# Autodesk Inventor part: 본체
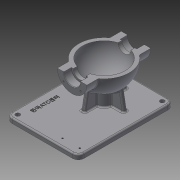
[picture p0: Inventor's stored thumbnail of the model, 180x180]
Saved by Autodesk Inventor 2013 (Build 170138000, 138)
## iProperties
Created: 2015-12
Part Number: 본체
Material: 일반
Document SubType Name: Modeling
Designer: mduedu
Density: 2.71 g/cm^3
Mass: 1330.63 g
Surface Area: 1128.56 cm^2
Volume: 491.008 cm^3
Author: mduedu
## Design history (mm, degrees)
sketch "스케치1"
  geometry: L1 (-53, 0)-(53, 0); A1 r 53 centre (0, 0) between (53, 0) and (-53, 0); 2 further points
  constraints: 2 coincident, 2 end point, 2 point on circle, 1 centre point, 1 horizontal, 1 midpoint
  dimensions: "d0" = 53 radius of A1
revolve "회전1" sketch "스케치1" stored, may be unused: angle "d2" = 90 deg
feature "쉘1" dims "d11" = 8
node "작업 평면1"
sketch "스케치2"
  geometry: C1 r 31 at (0, 0); 1 further point
  constraints: 1 centre point, 1 coincident
  dimensions: "d4" = 62 diameter of C1
extrude "돌출1" join sketch "스케치2" stored distance "d5" = 10; taper "d6" = 0 deg
hole "구멍1" diameter "d14" = 35; stored, may be unused: countersink angle "d18" = 90 deg, drill point angle "d20" = 0 deg; dims "d12" = 10, "d13" = 10, "d15" = 6, "d16" = 4, "d17" = 2, "d19" = 16
hole "구멍2" diameter "d23" = 27; stored, may be unused: countersink angle "d27" = 90 deg, drill point angle "d29" = 0 deg; dims "d21" = 10, "d22" = 10, "d24" = 6, "d25" = 4, "d26" = 2, "d28" = 16
fillet "모깎기1" dims "d30" = 0.3
chamfer "모따기1" distance "d40" = 1; stored, may be unused: second distance "d41" = 2, angle "d42" = 45 deg
sketch "스케치4"
  geometry: L1 (0, 0)-(0, -25); L2 (0, 0)-(-17.678, -17.678); A1 r 25 centre (0, 0) between (-17.678, -17.678) and (0, -25); 1 further point
  constraints: 4 end point, 2 point on circle, 1 centre point, 1 coincident, 1 vertical
  dimensions: "d43" = 50 diameter of A1; "d47" = 45 deg angle of L1 L2
hole "구멍4" sketch "스케치4" at (-17.678, -17.678) diameter "d49" = 3.242; stored, may be unused: countersink angle "d53" = 90 deg, drill point angle "d55" = 118 deg; dims "d50" = 11, "d51" = 4, "d52" = 2, "d54" = 13
node "작업 평면3"
sketch "스케치6" dims "d21" = 10, "d22" = 10
  geometry: L1 (-70, -75)-(130, -75); L2 (130, -75)-(130, 76); L3 (130, 76)-(-70, 76); L4 (-70, 76)-(-70, -75); 2 further points
  constraints: 8 end point, 2 parallel, 1 coincident, 1 horizontal, 1 perpendicular
  dimensions: "d158" = 200 distance of L3.end L2.end; "d159" = 151 distance of L2.end L1.end; "d162" = 75 distance from line of L1 point (0, 0); "d163" = 70 distance from line of L4 point (0, 0)
extrude "돌출3" join sketch "스케치6" distance "d80" = 10; taper "d81" = 0 deg
sketch "스케치7"
  geometry: C1 r 20 at (0, 0); 2 further points
  constraints: 2 coincident, 1 centre point
  dimensions: "d82" = 40 diameter of C1
extrude "돌출4" join sketch "스케치7" stored distance "d84" = 10; taper "d85" = 0 deg
sketch "스케치8"
  geometry: 3 further points
  constraints: 2 coincident
hole "구멍6" sketch "스케치8" at (0, 0) diameter "d86" = 20; stored, may be unused: countersink angle "d90" = 90 deg, drill point angle "d92" = 118 deg; dims "d87" = 7, "d88" = 40, "d89" = 5, "d91" = 10
fillet "모깎기2" dims "d93" = 0.3
sketch "스케치9"
  geometry: L1 (-45, -75)-(-38.245, -36.692); L2 (70, -75)-(-130, -75) reference; A1 r 53 centre (0, 0) between (42.988, 31) and (42.988, -31) reference; 1 further point
  constraints: 2 end point, 1 coincident, 1 point on circle, 1 point on line
  dimensions: "d94" = 45 horizontal distance of L1.start point (0, 0); "d160" = 80 deg angle of L2 L1
feature "리브1" sketch "스케치9" dims "d96" = 1, "d97" = 8, "d98" = 0, "d99" = 0, "d100" = 1, "d101" = 1
fillet "모깎기3" dims "d120" = 3
fillet "모깎기4" dims "d121" = 3, "d122" = 3
fillet "모깎기5" dims "d123" = 3
sketch "스케치12"
  geometry: L1 (0, 100)-(0, -100); L2 (0, 100)-(100, 100); L3 (100, 100)-(100, -100); L4 (100, -100)-(0, -100); 2 further points
  constraints: 8 end point, 3 perpendicular, 1 coincident, 1 midpoint, 1 vertical
  dimensions: "d127" = 200 distance of L2.end L3.end; "d129" = 100 distance between parallel lines of L1 L3
extrude "돌출5" cut sketch "스케치12" stored distance "d130" = 10; taper "d131" = 0 deg
fillet "모깎기10" dims "d164" = 12
fillet "모깎기11" dims "d165" = 3
sketch "스케치15"
  geometry: C1 r 4.5 at (-118, 63); C2 r 4.5 at (58, 63); C3 r 4.5 at (58, -64); A1 r 12 centre (-118, 63) between (-118, 75) and (-130, 63) reference; A2 r 12 centre (58, 63) between (70, 63) and (58, 75) reference; A3 r 12 centre (58, -64) between (58, -76) and (70, -64) reference; 1 further point
  constraints: 3 centre point, 3 coincident, 2 equal radius
  dimensions: "d166" = 9 diameter of C1
extrude "돌출8" cut sketch "스케치15" stored distance "d167" = 10; taper "d168" = 0 deg
sketch "스케치16"
  geometry: L1 (-130, 63)-(-130, -64) reference; L2 (-118, -76)-(58, -76) reference; 2 further points
  constraints: 1 other
  dimensions: "d169" = 60 distance from line of point (-70, 54) L1; "d170" = 130 distance from line of point (-70, 54) L2
feature "엠보싱2" sketch "스케치16" dims "d171" = 0.5, "d172" = 0
sketch "스케치17"
  geometry: L1 (-118, 76)-(58, 76) reference; L2 (-130, -63)-(-130, 64) reference; 2 further points
  constraints: 1 vertical alignment
  dimensions: "d180" = 13 distance from line of L1 point (-114, 63); "d181" = 16 distance from line of point (-114, 63) L2; "d182" = 36 distance of point (-114, 27) point (-114, 63)
hole "구멍9" sketch "스케치17" at (-114, 63), (-114, 27) diameter "d173" = 3.242; stored, may be unused: countersink angle "d177" = 90 deg, drill point angle "d179" = 0 deg; dims "d174" = 6, "d175" = 4, "d176" = 2, "d178" = 8
node "솔리드1"
mirror "대칭1"
mirror "대칭2"
pattern_circular "원형 패턴1" dims angle "d57" = 360 deg
mirror "대칭3"
pattern_circular "원형 패턴3" dims angle "d103" = 360 deg
other parameters: "d3" = 67, "d77" = -85
